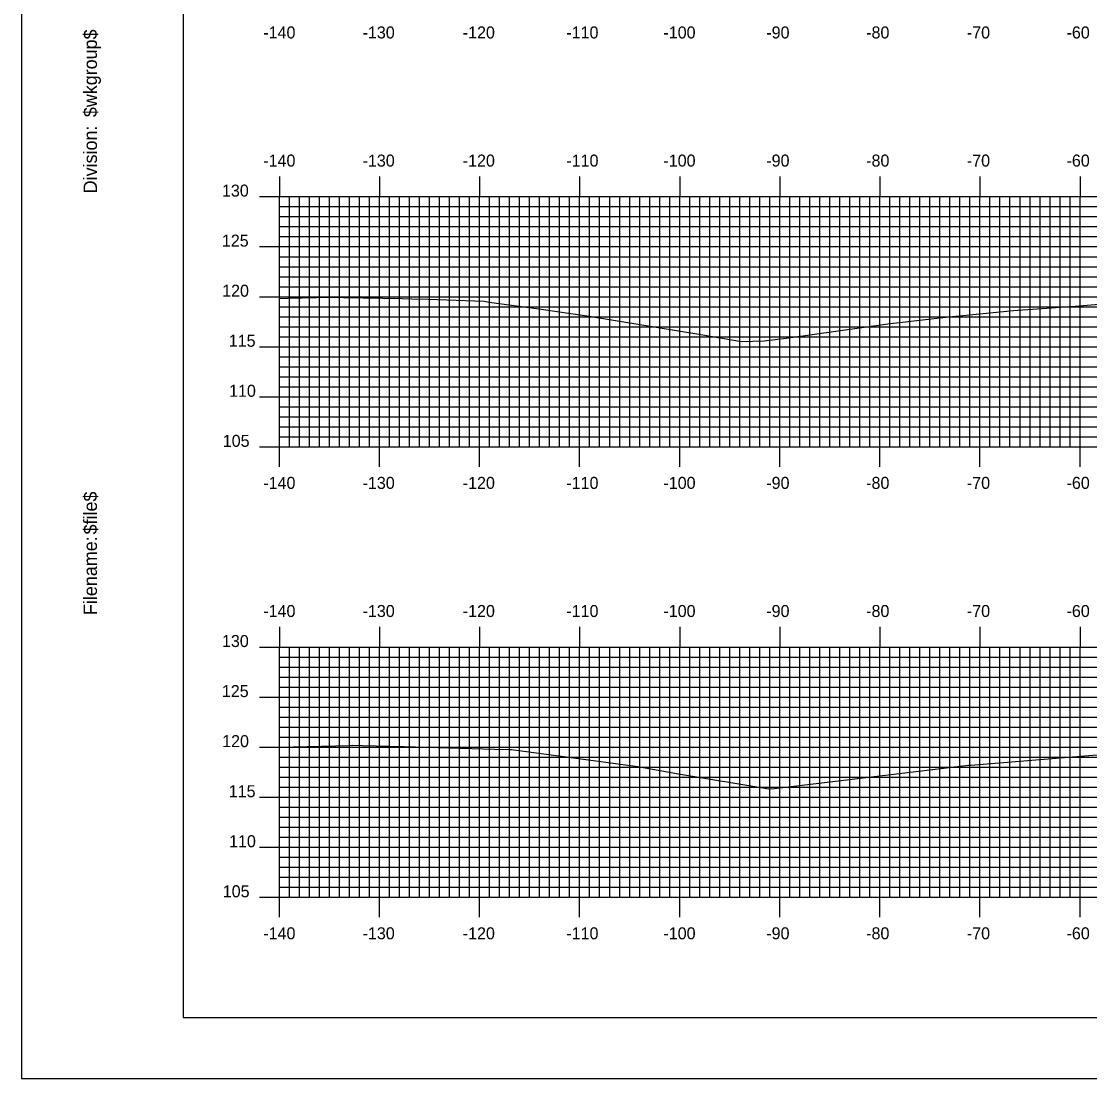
# Model space of a CAD drawing. Extents: x 844536 to 844879, y 363538 to 363758.
# Drawn here: x 844536.2 to 844642.9, y 363537.6 to 363643.2 of the extents above; entities that cross this region are included whole.
import ezdxf

# ---------------------------------------------------------------- set-up
doc = ezdxf.new("R2010")
doc.units = 0
for name, color, linetype in [('BORDER', 7, 'Continuous'), ('H_V ANNOTATION', 7, 'Continuous'), ('M_Roadway_Centerline', 7, 'Continuous'), ('MAJOR', 7, 'Continuous'), ('MINOR', 7, 'Continuous'), ('PLOT BOUNDARY', 7, 'Continuous'), ('S_Roadway_Centerline', 7, 'Continuous')]:
    doc.layers.add(name, color=color, linetype=linetype)

msp = doc.modelspace()

# ---------------------------------------------------------------- linework, layer by layer
at = {"layer": 'BORDER'}
msp.add_lwpolyline([(844552.36, 363543.72), (844872.36, 363543.72), (844872.36, 363753.72), (844552.36, 363753.72)], close=True, dxfattribs=at)
at = {"layer": 'MAJOR'}
for p, q in [((844561.96, 363627.73), (844561.96, 363625.72)), ((844571.96, 363627.73), (844571.96, 363625.72)), ((844581.96, 363627.73), (844581.96, 363625.72)), ((844591.96, 363627.73), (844591.96, 363625.72)), ((844601.96, 363627.73), (844601.96, 363625.72)), ((844611.96, 363627.73), (844611.96, 363625.72)), ((844621.96, 363627.73), (844621.96, 363625.72)), ((844631.96, 363627.73), (844631.96, 363625.72)), ((844641.96, 363627.73), (844641.96, 363625.72)), ((844559.96, 363625.72), (844561.96, 363625.72)), ((844561.96, 363625.72), (844841.96, 363625.72)), ((844561.96, 363600.72), (844561.96, 363625.72)), ((844561.96, 363600.72), (844561.96, 363625.72)), ((844561.96, 363625.72), (844841.96, 363625.72)), ((844571.96, 363600.72), (844571.96, 363625.72)), ((844581.96, 363600.72), (844581.96, 363625.72)), ((844591.96, 363600.72), (844591.96, 363625.72)), ((844601.96, 363600.72), (844601.96, 363625.72)), ((844611.96, 363600.72), (844611.96, 363625.72)), ((844621.96, 363600.72), (844621.96, 363625.72)), ((844631.96, 363600.72), (844631.96, 363625.72)), ((844641.96, 363600.72), (844641.96, 363625.72)), ((844559.96, 363620.72), (844561.96, 363620.72)), ((844561.96, 363620.72), (844841.96, 363620.72)), ((844559.96, 363615.72), (844561.96, 363615.72)), ((844561.96, 363615.72), (844841.96, 363615.72)), ((844559.96, 363610.72), (844561.96, 363610.72)), ((844561.96, 363610.72), (844841.96, 363610.72)), ((844559.96, 363605.72), (844561.96, 363605.72)), ((844561.96, 363605.72), (844841.96, 363605.72)), ((844559.96, 363600.72), (844561.96, 363600.72)), ((844561.96, 363600.72), (844841.96, 363600.72)), ((844561.96, 363600.72), (844841.96, 363600.72)), ((844561.96, 363598.72), (844561.96, 363600.72)), ((844571.96, 363598.72), (844571.96, 363600.72)), ((844581.96, 363598.72), (844581.96, 363600.72)), ((844591.96, 363598.72), (844591.96, 363600.72)), ((844601.96, 363598.72), (844601.96, 363600.72)), ((844611.96, 363598.72), (844611.96, 363600.72)), ((844621.96, 363598.72), (844621.96, 363600.72)), ((844631.96, 363598.72), (844631.96, 363600.72)), ((844641.96, 363598.72), (844641.96, 363600.72)), ((844561.96, 363582.73), (844561.96, 363580.72)), ((844571.96, 363582.73), (844571.96, 363580.72)), ((844581.96, 363582.73), (844581.96, 363580.72)), ((844591.96, 363582.73), (844591.96, 363580.72)), ((844601.96, 363582.73), (844601.96, 363580.72)), ((844611.96, 363582.73), (844611.96, 363580.72)), ((844621.96, 363582.73), (844621.96, 363580.72)), ((844631.96, 363582.73), (844631.96, 363580.72)), ((844641.96, 363582.73), (844641.96, 363580.72)), ((844559.96, 363580.72), (844561.96, 363580.72)), ((844561.96, 363580.72), (844841.96, 363580.72)), ((844561.96, 363555.72), (844561.96, 363580.72)), ((844561.96, 363555.72), (844561.96, 363580.72)), ((844561.96, 363580.72), (844841.96, 363580.72)), ((844571.96, 363555.72), (844571.96, 363580.72)), ((844581.96, 363555.72), (844581.96, 363580.72)), ((844591.96, 363555.72), (844591.96, 363580.72)), ((844601.96, 363555.72), (844601.96, 363580.72)), ((844611.96, 363555.72), (844611.96, 363580.72)), ((844621.96, 363555.72), (844621.96, 363580.72)), ((844631.96, 363555.72), (844631.96, 363580.72)), ((844641.96, 363555.72), (844641.96, 363580.72)), ((844559.96, 363575.72), (844561.96, 363575.72)), ((844561.96, 363575.72), (844841.96, 363575.72)), ((844559.96, 363570.72), (844561.96, 363570.72)), ((844561.96, 363570.72), (844841.96, 363570.72)), ((844559.96, 363565.72), (844561.96, 363565.72)), ((844561.96, 363565.72), (844841.96, 363565.72)), ((844559.96, 363560.72), (844561.96, 363560.72)), ((844561.96, 363560.72), (844841.96, 363560.72)), ((844559.96, 363555.72), (844561.96, 363555.72)), ((844561.96, 363555.72), (844841.96, 363555.72)), ((844561.96, 363555.72), (844841.96, 363555.72)), ((844561.96, 363553.72), (844561.96, 363555.72)), ((844571.96, 363553.72), (844571.96, 363555.72)), ((844581.96, 363553.72), (844581.96, 363555.72)), ((844591.96, 363553.72), (844591.96, 363555.72)), ((844601.96, 363553.72), (844601.96, 363555.72)), ((844611.96, 363553.72), (844611.96, 363555.72)), ((844621.96, 363553.72), (844621.96, 363555.72)), ((844631.96, 363553.72), (844631.96, 363555.72)), ((844641.96, 363553.72), (844641.96, 363555.72))]:
    msp.add_line(p, q, dxfattribs=at)
at = {"layer": 'MINOR'}
for p, q in [((844562.96, 363600.72), (844562.96, 363625.72)), ((844563.96, 363600.72), (844563.96, 363625.72)), ((844564.96, 363600.72), (844564.96, 363625.72)), ((844565.96, 363600.72), (844565.96, 363625.72)), ((844566.96, 363600.72), (844566.96, 363625.72)), ((844567.96, 363600.72), (844567.96, 363625.72)), ((844568.96, 363600.72), (844568.96, 363625.72)), ((844569.96, 363600.72), (844569.96, 363625.72)), ((844570.96, 363600.72), (844570.96, 363625.72)), ((844572.96, 363600.72), (844572.96, 363625.72)), ((844573.96, 363600.72), (844573.96, 363625.72)), ((844574.96, 363600.72), (844574.96, 363625.72)), ((844575.96, 363600.72), (844575.96, 363625.72)), ((844576.96, 363600.72), (844576.96, 363625.72)), ((844577.96, 363600.72), (844577.96, 363625.72)), ((844578.96, 363600.72), (844578.96, 363625.72)), ((844579.96, 363600.72), (844579.96, 363625.72)), ((844580.96, 363600.72), (844580.96, 363625.72)), ((844582.96, 363600.72), (844582.96, 363625.72)), ((844583.96, 363600.72), (844583.96, 363625.72)), ((844584.96, 363600.72), (844584.96, 363625.72)), ((844585.96, 363600.72), (844585.96, 363625.72)), ((844586.96, 363600.72), (844586.96, 363625.72)), ((844587.96, 363600.72), (844587.96, 363625.72)), ((844588.96, 363600.72), (844588.96, 363625.72)), ((844589.96, 363600.72), (844589.96, 363625.72)), ((844590.96, 363600.72), (844590.96, 363625.72)), ((844592.96, 363600.72), (844592.96, 363625.72)), ((844593.96, 363600.72), (844593.96, 363625.72)), ((844594.96, 363600.72), (844594.96, 363625.72)), ((844595.96, 363600.72), (844595.96, 363625.72)), ((844596.96, 363600.72), (844596.96, 363625.72)), ((844597.96, 363600.72), (844597.96, 363625.72)), ((844598.96, 363600.72), (844598.96, 363625.72)), ((844599.96, 363600.72), (844599.96, 363625.72)), ((844600.96, 363600.72), (844600.96, 363625.72)), ((844602.96, 363600.72), (844602.96, 363625.72)), ((844603.96, 363600.72), (844603.96, 363625.72)), ((844604.96, 363600.72), (844604.96, 363625.72)), ((844605.96, 363600.72), (844605.96, 363625.72)), ((844606.96, 363600.72), (844606.96, 363625.72)), ((844607.96, 363600.72), (844607.96, 363625.72)), ((844608.96, 363600.72), (844608.96, 363625.72)), ((844609.96, 363600.72), (844609.96, 363625.72)), ((844610.96, 363600.72), (844610.96, 363625.72)), ((844612.96, 363600.72), (844612.96, 363625.72)), ((844613.96, 363600.72), (844613.96, 363625.72)), ((844614.96, 363600.72), (844614.96, 363625.72)), ((844615.96, 363600.72), (844615.96, 363625.72)), ((844616.96, 363600.72), (844616.96, 363625.72)), ((844617.96, 363600.72), (844617.96, 363625.72)), ((844618.96, 363600.72), (844618.96, 363625.72)), ((844619.96, 363600.72), (844619.96, 363625.72)), ((844620.96, 363600.72), (844620.96, 363625.72)), ((844622.96, 363600.72), (844622.96, 363625.72)), ((844623.96, 363600.72), (844623.96, 363625.72)), ((844624.96, 363600.72), (844624.96, 363625.72)), ((844625.96, 363600.72), (844625.96, 363625.72)), ((844626.96, 363600.72), (844626.96, 363625.72)), ((844627.96, 363600.72), (844627.96, 363625.72)), ((844628.96, 363600.72), (844628.96, 363625.72)), ((844629.96, 363600.72), (844629.96, 363625.72)), ((844630.96, 363600.72), (844630.96, 363625.72)), ((844632.96, 363600.72), (844632.96, 363625.72)), ((844633.96, 363600.72), (844633.96, 363625.72)), ((844634.96, 363600.72), (844634.96, 363625.72)), ((844635.96, 363600.72), (844635.96, 363625.72)), ((844636.96, 363600.72), (844636.96, 363625.72)), ((844637.96, 363600.72), (844637.96, 363625.72)), ((844638.96, 363600.72), (844638.96, 363625.72)), ((844639.96, 363600.72), (844639.96, 363625.72)), ((844640.96, 363600.72), (844640.96, 363625.72)), ((844561.96, 363624.72), (844841.96, 363624.72)), ((844561.96, 363624.72), (844563.97, 363624.72)), ((844561.96, 363623.72), (844841.96, 363623.72)), ((844561.96, 363623.72), (844563.97, 363623.72)), ((844561.96, 363622.72), (844841.96, 363622.72)), ((844561.96, 363622.72), (844563.97, 363622.72)), ((844561.96, 363621.72), (844841.96, 363621.72)), ((844561.96, 363621.72), (844563.97, 363621.72)), ((844561.96, 363619.72), (844841.96, 363619.72)), ((844561.96, 363619.72), (844563.97, 363619.72)), ((844561.96, 363618.72), (844841.96, 363618.72)), ((844561.96, 363618.72), (844563.97, 363618.72)), ((844561.96, 363617.72), (844841.96, 363617.72)), ((844561.96, 363617.72), (844563.97, 363617.72)), ((844561.96, 363616.72), (844841.96, 363616.72)), ((844561.96, 363616.72), (844563.97, 363616.72)), ((844561.96, 363614.72), (844841.96, 363614.72)), ((844561.96, 363614.72), (844563.97, 363614.72)), ((844561.96, 363613.72), (844841.96, 363613.72)), ((844561.96, 363613.72), (844563.97, 363613.72)), ((844561.96, 363612.72), (844841.96, 363612.72)), ((844561.96, 363612.72), (844563.97, 363612.72)), ((844561.96, 363611.72), (844841.96, 363611.72)), ((844561.96, 363611.72), (844563.97, 363611.72)), ((844561.96, 363609.72), (844841.96, 363609.72)), ((844561.96, 363609.72), (844563.97, 363609.72)), ((844561.96, 363608.72), (844841.96, 363608.72)), ((844561.96, 363608.72), (844563.97, 363608.72)), ((844561.96, 363607.72), (844841.96, 363607.72)), ((844561.96, 363607.72), (844563.97, 363607.72)), ((844561.96, 363606.72), (844841.96, 363606.72)), ((844561.96, 363606.72), (844563.97, 363606.72)), ((844561.96, 363604.72), (844841.96, 363604.72)), ((844561.96, 363604.72), (844563.97, 363604.72)), ((844561.96, 363603.72), (844841.96, 363603.72)), ((844561.96, 363603.72), (844563.97, 363603.72)), ((844561.96, 363602.72), (844841.96, 363602.72)), ((844561.96, 363602.72), (844563.97, 363602.72)), ((844561.96, 363601.72), (844841.96, 363601.72)), ((844561.96, 363601.72), (844563.97, 363601.72)), ((844562.96, 363555.72), (844562.96, 363580.72)), ((844563.96, 363555.72), (844563.96, 363580.72)), ((844564.96, 363555.72), (844564.96, 363580.72)), ((844565.96, 363555.72), (844565.96, 363580.72)), ((844566.96, 363555.72), (844566.96, 363580.72)), ((844567.96, 363555.72), (844567.96, 363580.72)), ((844568.96, 363555.72), (844568.96, 363580.72)), ((844569.96, 363555.72), (844569.96, 363580.72)), ((844570.96, 363555.72), (844570.96, 363580.72)), ((844572.96, 363555.72), (844572.96, 363580.72)), ((844573.96, 363555.72), (844573.96, 363580.72)), ((844574.96, 363555.72), (844574.96, 363580.72)), ((844575.96, 363555.72), (844575.96, 363580.72)), ((844576.96, 363555.72), (844576.96, 363580.72)), ((844577.96, 363555.72), (844577.96, 363580.72)), ((844578.96, 363555.72), (844578.96, 363580.72)), ((844579.96, 363555.72), (844579.96, 363580.72)), ((844580.96, 363555.72), (844580.96, 363580.72)), ((844582.96, 363555.72), (844582.96, 363580.72)), ((844583.96, 363555.72), (844583.96, 363580.72)), ((844584.96, 363555.72), (844584.96, 363580.72)), ((844585.96, 363555.72), (844585.96, 363580.72)), ((844586.96, 363555.72), (844586.96, 363580.72)), ((844587.96, 363555.72), (844587.96, 363580.72)), ((844588.96, 363555.72), (844588.96, 363580.72)), ((844589.96, 363555.72), (844589.96, 363580.72)), ((844590.96, 363555.72), (844590.96, 363580.72)), ((844592.96, 363555.72), (844592.96, 363580.72)), ((844593.96, 363555.72), (844593.96, 363580.72)), ((844594.96, 363555.72), (844594.96, 363580.72)), ((844595.96, 363555.72), (844595.96, 363580.72)), ((844596.96, 363555.72), (844596.96, 363580.72)), ((844597.96, 363555.72), (844597.96, 363580.72)), ((844598.96, 363555.72), (844598.96, 363580.72)), ((844599.96, 363555.72), (844599.96, 363580.72)), ((844600.96, 363555.72), (844600.96, 363580.72)), ((844602.96, 363555.72), (844602.96, 363580.72)), ((844603.96, 363555.72), (844603.96, 363580.72)), ((844604.96, 363555.72), (844604.96, 363580.72)), ((844605.96, 363555.72), (844605.96, 363580.72)), ((844606.96, 363555.72), (844606.96, 363580.72)), ((844607.96, 363555.72), (844607.96, 363580.72)), ((844608.96, 363555.72), (844608.96, 363580.72)), ((844609.96, 363555.72), (844609.96, 363580.72)), ((844610.96, 363555.72), (844610.96, 363580.72)), ((844612.96, 363555.72), (844612.96, 363580.72)), ((844613.96, 363555.72), (844613.96, 363580.72)), ((844614.96, 363555.72), (844614.96, 363580.72)), ((844615.96, 363555.72), (844615.96, 363580.72)), ((844616.96, 363555.72), (844616.96, 363580.72)), ((844617.96, 363555.72), (844617.96, 363580.72)), ((844618.96, 363555.72), (844618.96, 363580.72)), ((844619.96, 363555.72), (844619.96, 363580.72)), ((844620.96, 363555.72), (844620.96, 363580.72)), ((844622.96, 363555.72), (844622.96, 363580.72)), ((844623.96, 363555.72), (844623.96, 363580.72)), ((844624.96, 363555.72), (844624.96, 363580.72)), ((844625.96, 363555.72), (844625.96, 363580.72)), ((844626.96, 363555.72), (844626.96, 363580.72)), ((844627.96, 363555.72), (844627.96, 363580.72)), ((844628.96, 363555.72), (844628.96, 363580.72)), ((844629.96, 363555.72), (844629.96, 363580.72)), ((844630.96, 363555.72), (844630.96, 363580.72)), ((844632.96, 363555.72), (844632.96, 363580.72)), ((844633.96, 363555.72), (844633.96, 363580.72)), ((844634.96, 363555.72), (844634.96, 363580.72)), ((844635.96, 363555.72), (844635.96, 363580.72)), ((844636.96, 363555.72), (844636.96, 363580.72)), ((844637.96, 363555.72), (844637.96, 363580.72)), ((844638.96, 363555.72), (844638.96, 363580.72)), ((844639.96, 363555.72), (844639.96, 363580.72)), ((844640.96, 363555.72), (844640.96, 363580.72)), ((844561.96, 363579.72), (844841.96, 363579.72)), ((844561.96, 363579.72), (844563.97, 363579.72)), ((844561.96, 363578.72), (844841.96, 363578.72)), ((844561.96, 363578.72), (844563.97, 363578.72)), ((844561.96, 363577.72), (844841.96, 363577.72)), ((844561.96, 363577.72), (844563.97, 363577.72)), ((844561.96, 363576.72), (844841.96, 363576.72)), ((844561.96, 363576.72), (844563.97, 363576.72)), ((844561.96, 363574.72), (844841.96, 363574.72)), ((844561.96, 363574.72), (844563.97, 363574.72)), ((844561.96, 363573.72), (844841.96, 363573.72)), ((844561.96, 363573.72), (844563.97, 363573.72)), ((844561.96, 363572.72), (844841.96, 363572.72)), ((844561.96, 363572.72), (844563.97, 363572.72)), ((844561.96, 363571.72), (844841.96, 363571.72)), ((844561.96, 363571.72), (844563.97, 363571.72)), ((844561.96, 363569.72), (844841.96, 363569.72)), ((844561.96, 363569.72), (844563.97, 363569.72)), ((844561.96, 363568.72), (844841.96, 363568.72)), ((844561.96, 363568.72), (844563.97, 363568.72)), ((844561.96, 363567.72), (844841.96, 363567.72)), ((844561.96, 363567.72), (844563.97, 363567.72)), ((844561.96, 363566.72), (844841.96, 363566.72)), ((844561.96, 363566.72), (844563.97, 363566.72)), ((844561.96, 363564.72), (844841.96, 363564.72)), ((844561.96, 363564.72), (844563.97, 363564.72)), ((844561.96, 363563.72), (844841.96, 363563.72)), ((844561.96, 363563.72), (844563.97, 363563.72)), ((844561.96, 363562.72), (844841.96, 363562.72)), ((844561.96, 363562.72), (844563.97, 363562.72)), ((844561.96, 363561.72), (844841.96, 363561.72)), ((844561.96, 363561.72), (844563.97, 363561.72)), ((844561.96, 363559.72), (844841.96, 363559.72)), ((844561.96, 363559.72), (844563.97, 363559.72)), ((844561.96, 363558.72), (844841.96, 363558.72)), ((844561.96, 363558.72), (844563.97, 363558.72)), ((844561.96, 363557.72), (844841.96, 363557.72)), ((844561.96, 363557.72), (844563.97, 363557.72)), ((844561.96, 363556.72), (844841.96, 363556.72)), ((844561.96, 363556.72), (844563.97, 363556.72))]:
    msp.add_line(p, q, dxfattribs=at)
at = {"layer": 'PLOT BOUNDARY'}
msp.add_lwpolyline([(844536.18, 363537.6), (844876.18, 363537.6), (844876.18, 363757.6), (844536.18, 363757.6)], close=True, dxfattribs=at)
at = {"layer": 'S_Roadway_Centerline'}
for points in [[(844561.96, 363615.55), (844562.79, 363615.57), (844565.67, 363615.64), (844566.43, 363615.69), (844574.21, 363615.54), (844575.18, 363615.51), (844576.84, 363615.46), (844582.43, 363615.28), (844582.93, 363615.18), (844587.87, 363614.5), (844592.9, 363613.76), (844604.07, 363611.94), (844608.13, 363611.24), (844610.4, 363611.3), (844612.61, 363611.58), (844622.75, 363613.01), (844628.55, 363613.69), (844635.3, 363614.35), (844641.46, 363614.79), (844647.09, 363615.24)], [(844561.96, 363570.72), (844564.75, 363570.8), (844569.04, 363570.9), (844569.25, 363570.91), (844570.27, 363570.89), (844573.01, 363570.83), (844574.41, 363570.77), (844583.46, 363570.53), (844584.99, 363570.5), (844585.11, 363570.49), (844585.16, 363570.48), (844594.81, 363569.2), (844597.79, 363568.77), (844601.85, 363568.06), (844610.87, 363566.56), (844610.98, 363566.55), (844611.44, 363566.6), (844630.83, 363568.92), (844631.04, 363568.93), (844650.17, 363570.48)]]:
    msp.add_lwpolyline(points, dxfattribs=at)

# ---------------------------------------------------------------- texts
at = {"layer": 'BORDER'}
for s, p in [('$wkgroup$', (844543.73, 363633.66)), ('Division:', (844543.73, 363626.05)), ('$file$', (844543.73, 363591.97)), ('Filename:', (844543.73, 363583.92))]:
    msp.add_text(s, height=1.339, rotation=90, dxfattribs=at).set_placement(p)
at = {"layer": 'H_V ANNOTATION'}
for s, p in [('-140', (844560.35, 363641.52)), ('-130', (844570.27, 363641.52)), ('-120', (844580.28, 363641.52)), ('-110', (844590.63, 363641.52)), ('-100', (844600.33, 363641.52)), ('-90', (844610.61, 363641.52)), ('-80', (844620.59, 363641.52)), ('-70', (844630.65, 363641.52)), ('-60', (844640.61, 363641.52)), ('-140', (844560.35, 363628.72)), ('-130', (844570.27, 363628.72)), ('-120', (844580.28, 363628.72)), ('-110', (844590.63, 363628.72)), ('-100', (844600.33, 363628.72)), ('-90', (844610.61, 363628.72)), ('-80', (844620.59, 363628.72)), ('-70', (844630.65, 363628.72)), ('-60', (844640.61, 363628.72)), ('130', (844556.22, 363625.72)), ('125', (844556.21, 363620.72)), ('120', (844556.24, 363615.72)), ('115', (844556.9, 363610.72)), ('110', (844556.93, 363605.72)), ('105', (844556.3, 363600.72)), ('-140', (844560.35, 363596.52)), ('-130', (844570.27, 363596.52)), ('-120', (844580.28, 363596.52)), ('-110', (844590.63, 363596.52)), ('-100', (844600.33, 363596.52)), ('-90', (844610.61, 363596.52)), ('-80', (844620.59, 363596.52)), ('-70', (844630.65, 363596.52)), ('-60', (844640.61, 363596.52)), ('-140', (844560.35, 363583.72)), ('-130', (844570.27, 363583.72)), ('-120', (844580.28, 363583.72)), ('-110', (844590.63, 363583.72)), ('-100', (844600.33, 363583.72)), ('-90', (844610.61, 363583.72)), ('-80', (844620.59, 363583.72)), ('-70', (844630.65, 363583.72)), ('-60', (844640.61, 363583.72)), ('130', (844556.22, 363580.72)), ('125', (844556.21, 363575.72)), ('120', (844556.24, 363570.72)), ('115', (844556.9, 363565.72)), ('110', (844556.93, 363560.72)), ('105', (844556.3, 363555.72)), ('-140', (844560.35, 363551.52)), ('-130', (844570.27, 363551.52)), ('-120', (844580.28, 363551.52)), ('-110', (844590.63, 363551.52)), ('-100', (844600.33, 363551.52)), ('-90', (844610.61, 363551.52)), ('-80', (844620.59, 363551.52)), ('-70', (844630.65, 363551.52)), ('-60', (844640.61, 363551.52))]:
    msp.add_text(s, height=1.2, dxfattribs=at).set_placement(p)
at = {"layer": 'M_Roadway_Centerline'}
for s in ['C', 'L']:
    msp.add_text(s, height=0.0146, dxfattribs=at).set_placement((844566.43, 363615.69))
at = {"layer": 'MAJOR'}
for p in [(844561.95, 363600.72), (844561.95, 363555.72)]:
    msp.add_text('-', height=0.012, dxfattribs=at).set_placement(p)

doc.saveas('drawing.dxf')
